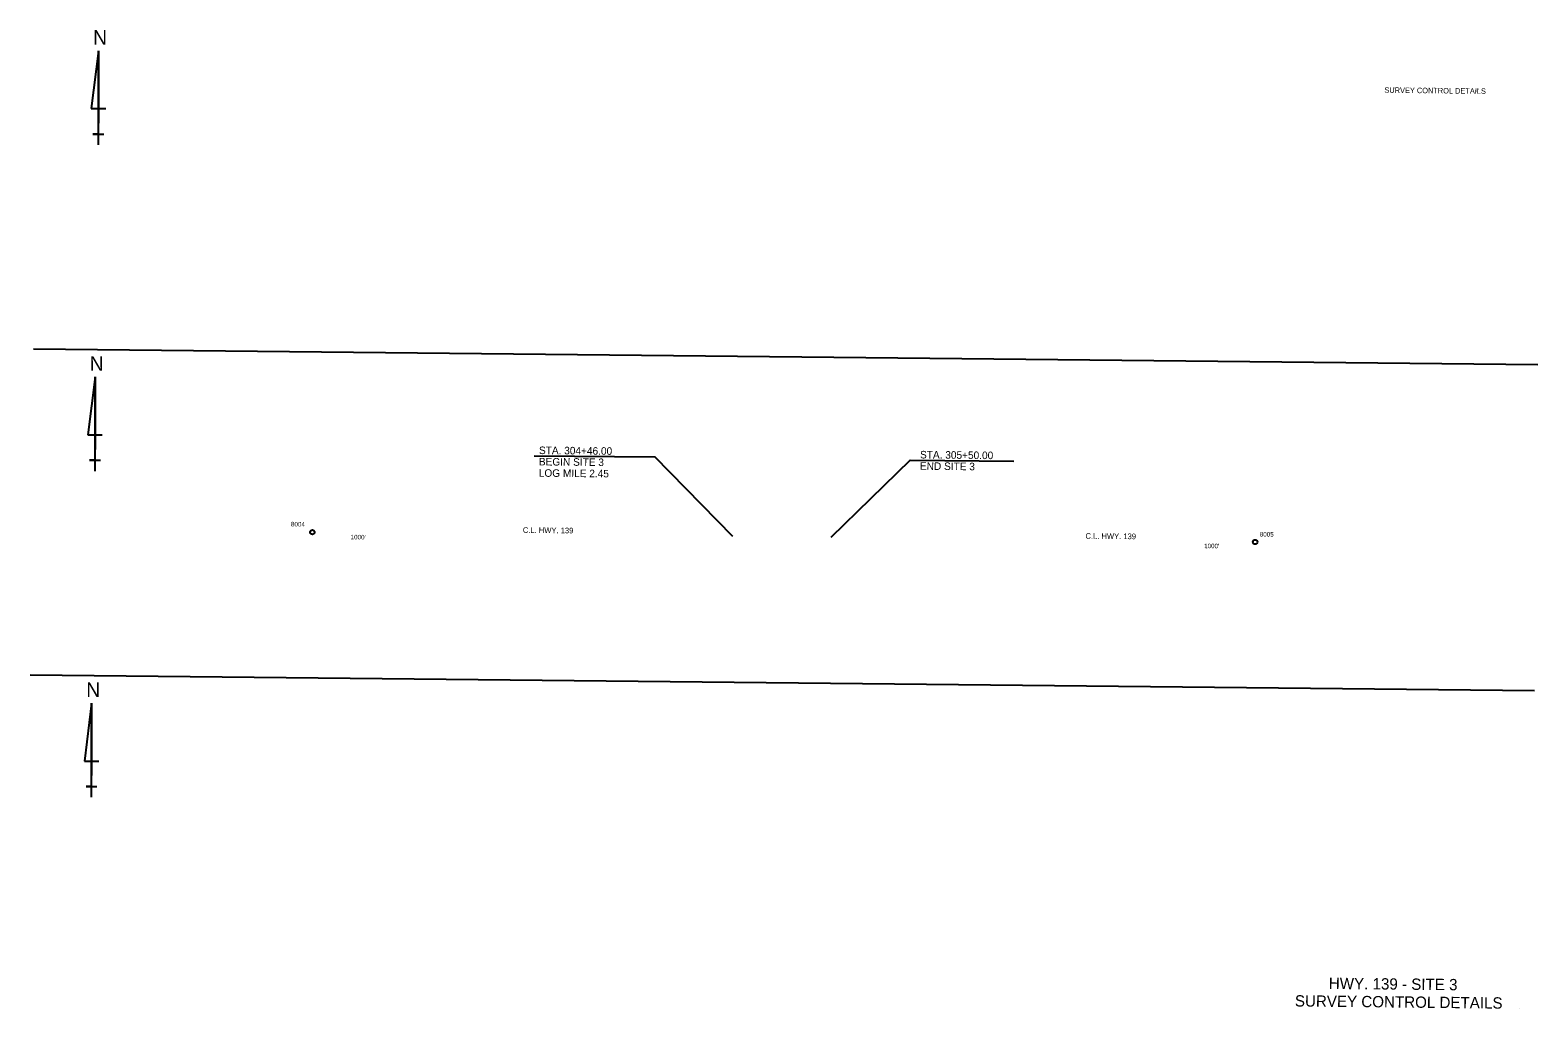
# Model space of a CAD drawing. Extents: x 1810130 to 1811728, y 532730 to 533769.
import ezdxf

# ---------------------------------------------------------------- set-up
doc = ezdxf.new("R2010")
doc.units = 0
for name, color, linetype in [('S_BASELINE', 7, 'Continuous'), ('S_SANITARY_SEWER', 7, 'Continuous'), ('S_SIDE_DRAIN', 7, 'Continuous')]:
    doc.layers.add(name, color=color, linetype=linetype)

msp = doc.modelspace()

# ---------------------------------------------------------------- linework, layer by layer
at = {"layer": 'S_BASELINE'}
for p, q in [((1810201.9, 533746.9), (1810194.2, 533685.4)), ((1810201.9, 533646.9), (1810201.9, 533746.9)), ((1810201.9, 533746.9), (1810201.9, 533670)), ((1810194.2, 533685.4), (1810209.6, 533685.4)), ((1810201.9, 533646.9), (1810201.9, 533670)), ((1810201.9, 533658.4), (1810196.1, 533658.4)), ((1810196.1, 533658.4), (1810207.7, 533658.4)), ((1810201.9, 533646.9), (1810201.9, 533658.4)), ((1810198.3, 533400.9), (1810190.6, 533339.4)), ((1810198.3, 533300.9), (1810198.3, 533400.9)), ((1810198.3, 533400.9), (1810198.3, 533324)), ((1810190.6, 533339.4), (1810206, 533339.4)), ((1810198.3, 533312.5), (1810192.5, 533312.5)), ((1810192.5, 533312.5), (1810204, 533312.5)), ((1810198.3, 533300.9), (1810198.3, 533324)), ((1810198.3, 533300.9), (1810198.3, 533312.5)), ((1810664, 533317.3), (1810792, 533315.9)), ((1810874.8, 533231.5), (1810792, 533315.9)), ((1811062.9, 533312.7), (1810978.8, 533230.4)), ((1811062.9, 533312.7), (1811172.8, 533311.6)), ((1810194.7, 533054.9), (1810187, 532993.4)), ((1810194.7, 532954.9), (1810194.7, 533054.9)), ((1810194.7, 533054.9), (1810194.7, 532978)), ((1810187, 532993.4), (1810202.3, 532993.4)), ((1810194.7, 532954.9), (1810194.7, 532978)), ((1810194.7, 532966.5), (1810188.9, 532966.5)), ((1810188.9, 532966.5), (1810200.4, 532966.5)), ((1810194.7, 532954.9), (1810194.7, 532966.5))]:
    msp.add_line(p, q, dxfattribs=at)
at = {"layer": 'S_SANITARY_SEWER'}
for centre in [(1810428.8, 533236.1), (1811428.7, 533225.7)]:
    msp.add_circle(centre, 2.38, dxfattribs=at)
at = {"layer": 'S_SIDE_DRAIN'}
for p, q in [((1810133.1, 533430.8), (1811728.4, 533414.1)), ((1810129.5, 533084.8), (1811724.8, 533068.2)), ((1811708.8, 532730.5), (1811708.8, 532730.5))]:
    msp.add_line(p, q, dxfattribs=at)

# ---------------------------------------------------------------- texts
at = {"layer": 'S_BASELINE'}
for s, height, rotation, p in [('N', 15.4, 360, (1810196.2, 533753.3)), ('N', 15.4, 360, (1810192.6, 533407.3)), ('STA. 304+46.00', 8, 359.4013, (1810669.1, 533319)), ('BEGIN SITE 3', 8, 359.4013, (1810669, 533307)), ('STA. 305+50.00', 8, 359.4013, (1811073.2, 533314.4)), ('END SITE 3', 8, 359.4013, (1811073.1, 533302.4)), ('LOG MILE 2.45', 8, 359.4013, (1810668.9, 533295)), ('8004', 4.8, 359.4013, (1810406.1, 533242.3)), ("1000'", 4.8, 359.4013, (1810469.4, 533228.6)), ('C.L. HWY. 139', 6, 359.4013, (1810652, 533235.4)), ('C.L. HWY. 139', 6, 359.4013, (1811248.7, 533229.2)), ('8005', 4.8, 359.4013, (1811433.5, 533231.6)), ("1000'", 4.8, 359.4013, (1811374.5, 533219.2)), ('N', 15.4, 360, (1810189, 533061.3)), ('HWY. 139 - SITE 3', 12, 359.4013, (1811506.7, 532751.6)), ('SURVEY CONTROL DETAILS', 12, 359.4013, (1811470.7, 532733))]:
    msp.add_text(s, height=height, rotation=rotation, dxfattribs=at).set_placement(p)
at = {"layer": 'S_SIDE_DRAIN'}
msp.add_text('SURVEY CONTROL DETAILS', height=5.862, rotation=359.4013, dxfattribs=at).set_placement((1811565.7, 533702.2))

doc.saveas('drawing.dxf')
